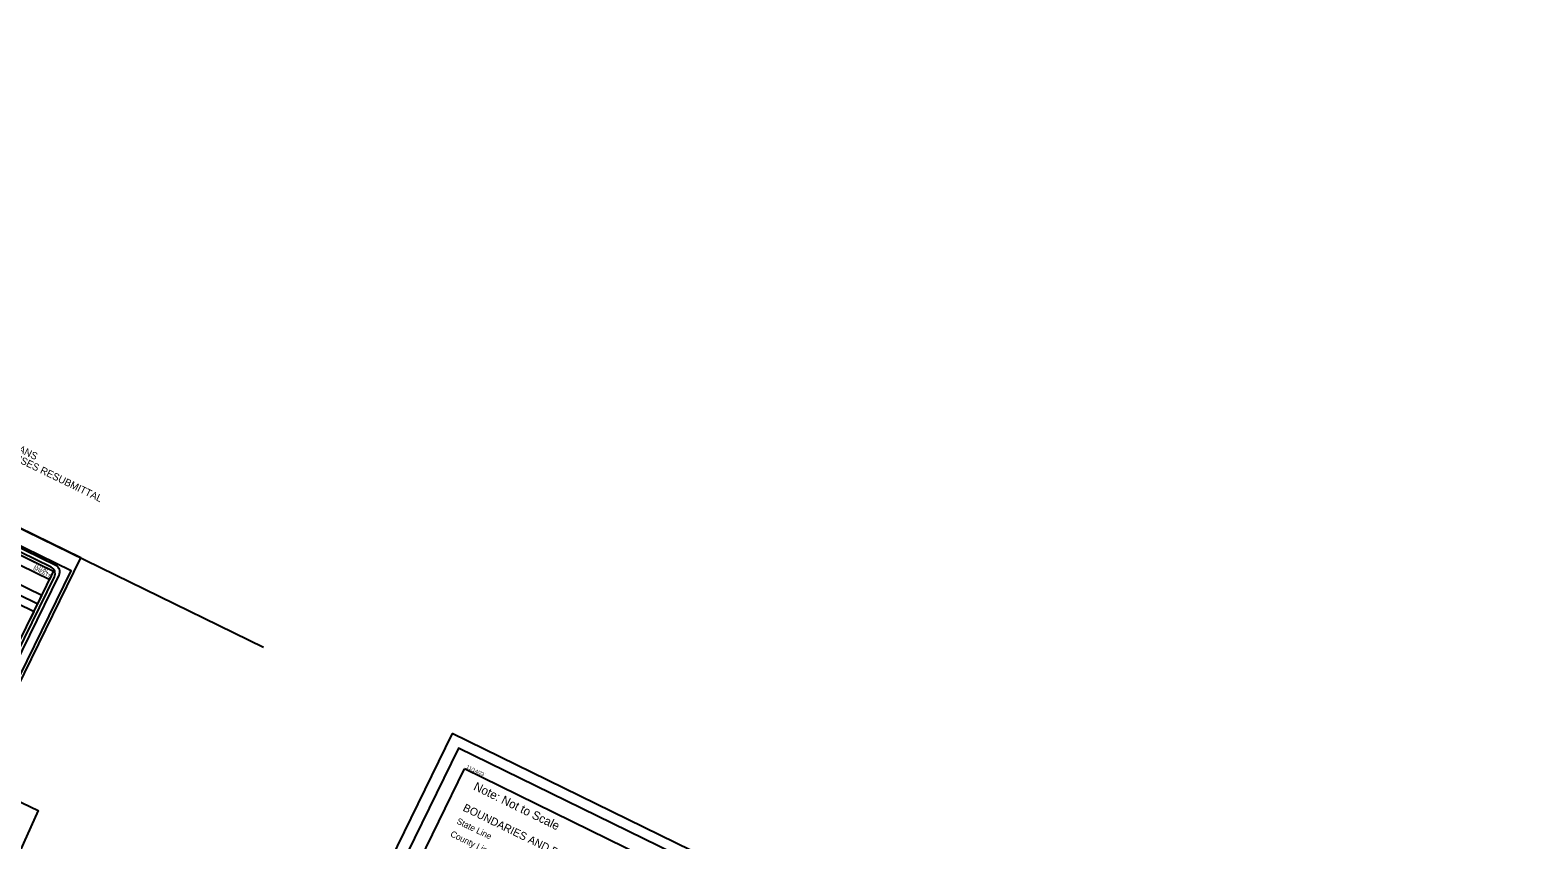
# Model space of a CAD drawing. Extents: x 1517888 to 1526099, y 633375 to 640181.
# Drawn here: x 1521738 to 1525964, y 637911 to 640181 of the extents above; entities that cross this region are included whole.
import ezdxf

# ---------------------------------------------------------------- set-up
doc = ezdxf.new("R2010")
doc.units = 0
for name, color, linetype in [('Default', 7, 'Continuous'), ('Sheet Clip Boundary CELL', 7, 'Continuous'), ('Sheet Cutting Line CELL', 7, 'Continuous'), ('Sheet Data Field CELL', 7, 'Continuous'), ('Sheet Plot Border Inside CELL', 7, 'Continuous'), ('Sheet Plot Border Outside CELL', 7, 'Continuous'), ('Sheet Title CELL', 7, 'Continuous')]:
    doc.layers.add(name, color=color, linetype=linetype)

msp = doc.modelspace()

# ---------------------------------------------------------------- linework, layer by layer
at = {"layer": 'Default'}
for p, q in [((1522921, 638209.2), (1521963.6, 636251.5)), ((1525946.6, 636729.5), (1522921, 638209.2)), ((1522062.9, 636285.6), (1522955.1, 638109.8)), ((1525847.2, 636695.4), (1522955.1, 638109.8)), ((1523015, 638097.2), (1523015, 638097.2))]:
    msp.add_line(p, q, dxfattribs=at)
at = {"layer": 'Sheet Clip Boundary CELL'}
msp.add_lwpolyline([(1519997.2, 638878.2), (1520677.9, 638519.7), (1521000.4, 638385.3), (1521102.7, 638308.6), (1521171, 638278.9), (1521396, 638166), (1521492.2, 638121.5), (1521760.4, 637993.1), (1521455.7, 637316.3), (1521359.7, 637143.3), (1520290, 637647.3), (1519534.4, 638030.1)], close=True, dxfattribs=at)
at = {"layer": 'Sheet Cutting Line CELL'}
msp.add_line((1519366.5, 639930.5), (1522392, 638450.7), dxfattribs=at)
at = {"layer": 'Sheet Plot Border Inside CELL'}
msp.add_lwpolyline([(1517931.1, 638233.4), (1520925.2, 636769.1), (1521852.3, 638664.7), (1518858.2, 640129.1)], close=True, dxfattribs=at)
at = {"layer": 'Sheet Plot Border Outside CELL'}
for points in [[(1521880.1, 638701.1), (1518854.6, 640180.8), (1517888, 638204.5), (1520913.6, 636724.8)], [(1525964.3, 636688.2), (1522938.8, 638168), (1521972.2, 636191.7), (1524997.7, 634712)]]:
    msp.add_lwpolyline(points, close=True, dxfattribs=at)
at = {"layer": 'Sheet Title CELL'}
for points in [[(1521809.7, 638679.9), (1519150.6, 639980.4)], [(1521796.3, 638675.3), (1519245.1, 639923.1)], [(1521298.5, 638882.1), (1521792.6, 638640.4), (1521803.5, 638662.9), (1521309.5, 638904.5)], [(1521265.5, 638814.7), (1521759.6, 638573), (1521770.6, 638595.5), (1521276.5, 638837.1)], [(1521737.6, 638528.1), (1521748.6, 638550.6), (1521254.5, 638792.2)], [(1521671.7, 638393.4), (1521803.5, 638662.9), (1521736.2, 638695.8)], [(1520913.8, 636802.6), (1521818.8, 638653.2)], [(1521071.7, 637148.4), (1521805.5, 638648.6)]]:
    msp.add_lwpolyline(points, dxfattribs=at)
for centre in [(1521787.5, 638657.4), (1521800.9, 638662)]:
    msp.add_arc(centre, 20, 333.9377, 63.9377, dxfattribs=at)

# ---------------------------------------------------------------- texts
at = {"layer": 'Default'}
for s, height, p in [('11/14/23', 9.91, (1522959.5, 638112.3)), ('Note: Not to Scale', 24.202, (1522978.6, 638052.5)), ('BOUNDARIES AND PROPERTY:', 21.988, (1522949, 637993.5)), ('State Line', 17.49, (1522931.5, 637957.6)), ('County Line', 17.49, (1522913.9, 637921.7))]:
    msp.add_text(s, height=height, rotation=333.9377, dxfattribs=at).set_placement(p)
at = {"layer": 'Sheet Data Field CELL'}
for s, p in [('RESPONSES RESUBMITTAL', (1521605.9, 639017.4)), ('65% PLANS', (1521617.5, 639041.2))]:
    msp.add_text(s, height=20.23, rotation=333.9377, dxfattribs=at).set_placement(p)
at = {"layer": 'Sheet Title CELL'}
for s, p in [('TOTAL', (1521748.1, 638678.5)), ('SHEETS', (1521744.3, 638669.3))]:
    msp.add_text(s, height=10, rotation=333.9377, dxfattribs=at).set_placement(p)

doc.saveas('drawing.dxf')
